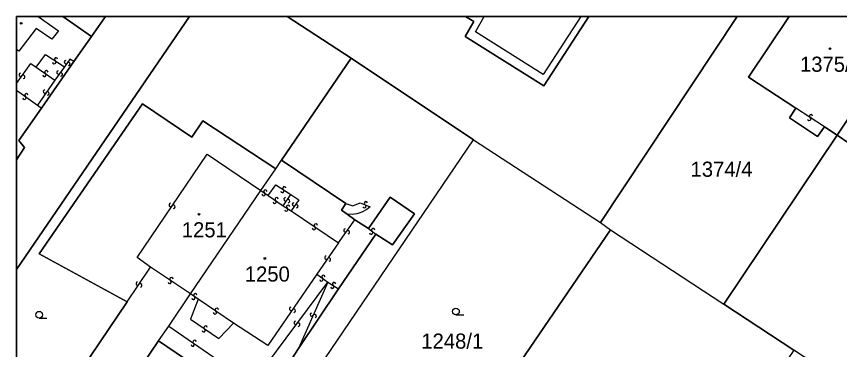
# Model space of a CAD drawing. Extents: x -600309 to -598967, y -1161267 to -1160292.
# Drawn here: x -600308.5 to -600216.2, y -1160329.8 to -1160292.3 of the extents above; entities that cross this region are included whole.
import ezdxf

# ---------------------------------------------------------------- set-up
doc = ezdxf.new("R2010")
doc.units = 0
for name, color, linetype in [('Level 1', 7, 'Continuous'), ('Level 13', 7, 'Continuous'), ('Level 3', 7, 'Continuous'), ('Level 4', 7, 'Continuous'), ('Level 5', 7, 'Continuous'), ('Level 60', 7, 'Continuous'), ('Vrstva 60', 7, 'Continuous'), ('Vrstva 63', 7, 'Continuous')]:
    doc.layers.add(name, color=color, linetype=linetype)

msp = doc.modelspace()

# ---------------------------------------------------------------- linework, layer by layer
at = {"layer": 'Level 1'}
for p, q in [((-600308.541, -1160320.794), (-600289.118, -1160292.347)), ((-600300.1, -1160294.6), (-600303.32, -1160292.347)), ((-600300.1, -1160294.6), (-600298.537, -1160292.347)), ((-600278.146, -1160292.347), (-600270.99, -1160297.05)), ((-600227.64, -1160292.347), (-600242.97, -1160315.51)), ((-600308.541, -1160342.846), (-600296.1, -1160324.42))]:
    msp.add_line(p, q, dxfattribs=at)
for points in [[(-600258.153, -1160292.347), (-600257.22, -1160292.93), (-600258.19, -1160294.6), (-600249.34, -1160300.14), (-600244.296, -1160292.347)], [(-600221.08, -1160302.65), (-600226.37, -1160299.17), (-600221.804, -1160292.347)], [(-600302.09, -1160297.42), (-600300.1, -1160294.6)], [(-600208.74, -1160294.23), (-600216.43, -1160305.71)], [(-600305.73, -1160302.65), (-600302.09, -1160297.42)], [(-600278.78, -1160308.52), (-600270.99, -1160297.05)], [(-600270.99, -1160297.05), (-600257.23, -1160306.23)], [(-600308.541, -1160308.453), (-600307.62, -1160307.07), (-600308.28, -1160306.3), (-600305.73, -1160302.65)], [(-600296.1, -1160324.42), (-600306, -1160319.03), (-600294.41, -1160302.17), (-600288.87, -1160305.93), (-600287.64, -1160304.09), (-600279.44, -1160309.47)], [(-600221.08, -1160302.65), (-600221.79, -1160303.73), (-600218.63, -1160305.86), (-600217.85, -1160304.77)], [(-600217.85, -1160304.77), (-600216.43, -1160305.71)], [(-600216.43, -1160305.71), (-600229.14, -1160324.7)], [(-600216.43, -1160305.71), (-600215.1, -1160306.58)], [(-600293.32, -1160359.44), (-600257.23, -1160306.23)], [(-600257.23, -1160306.23), (-600242.97, -1160315.51)], [(-600279.44, -1160309.47), (-600278.78, -1160308.52)], [(-600271.58, -1160313.38), (-600278.78, -1160308.52)], [(-600281.11, -1160311.9), (-600279.44, -1160309.47)], [(-600289, -1160323.54), (-600281.11, -1160311.9)], [(-600268.21, -1160316.83), (-600266.32, -1160318.03), (-600263.88, -1160314.52), (-600266.59, -1160312.66), (-600269.04, -1160316.19)], [(-600271.42, -1160314.57), (-600272.07, -1160314.13), (-600271.58, -1160313.38)], [(-600270.55, -1160315.2), (-600271.42, -1160314.57)], [(-600269.04, -1160316.19), (-600270.55, -1160315.2)], [(-600242.97, -1160315.51), (-600241.86, -1160316.33)], [(-600282.85, -1160376.42), (-600241.86, -1160316.33)], [(-600272.38, -1160322.95), (-600268.21, -1160316.83)], [(-600241.86, -1160316.33), (-600229.14, -1160324.7)], [(-600276.88, -1160329.68), (-600272.38, -1160322.95)], [(-600291.44, -1160327.18), (-600289, -1160323.54)], [(-600229.14, -1160324.7), (-600221.27, -1160329.87)], [(-600292.59, -1160328.82), (-600291.44, -1160327.18)], [(-600307.43, -1160350.76), (-600292.59, -1160328.82)], [(-600292.59, -1160328.82), (-600286.75, -1160332.8), (-600281.32, -1160334.59)], [(-600279.81, -1160334.2), (-600276.88, -1160329.68)]]:
    msp.add_lwpolyline(points, dxfattribs=at)
at = {"layer": 'Level 13'}
for centre, start, end in [((-600304.312, -1160297.483), 183.90701, 56.49701), ((-600304.107, -1160297.177), 4.12147, 236.21946), ((-600303, -1160297.484), 92.25578, 324.84578), ((-600302.7, -1160297.697), 272.47024, 144.56824), ((-600308.068, -1160298.91), 91.28301, 323.38101), ((-600307.772, -1160299.129), 271.06856, 143.65856), ((-600305.396, -1160298.921), 182.40614, 54.99614), ((-600305.183, -1160298.619), 2.6206, 234.71859), ((-600303.847, -1160298.65), 90.53695, 323.12695), ((-600303.553, -1160298.871), 270.75141, 142.8494), ((-600307.432, -1160301.2), 2.21265, 234.31065), ((-600305.362, -1160300.795), 92.8145, 325.4045), ((-600305.059, -1160301.005), 273.02895, 145.12695), ((-600307.647, -1160301.5), 181.99819, 54.58819), ((-600219.563, -1160303.863), 184.09397, 56.19197), ((-600219.358, -1160303.557), 3.87951, 236.46951), ((-600280.804, -1160312.332), 183.15079, 55.74079), ((-600280.595, -1160312.028), 3.36524, 235.46324), ((-600278.692, -1160311.973), 183.62781, 56.21781), ((-600278.487, -1160311.667), 3.84226, 235.94026), ((-600279.556, -1160313.191), 182.37402, 54.96402), ((-600279.343, -1160312.889), 2.58847, 234.68647), ((-600278.342, -1160312.895), 93.15703, 325.25503), ((-600278.038, -1160313.104), 272.94258, 145.53258), ((-600291.222, -1160313.535), 93.31946, 325.41746), ((-600290.918, -1160313.744), 273.10501, 145.69501), ((-600278.248, -1160314.056), 185.37736, 57.96736), ((-600278.051, -1160313.744), 5.59182, 237.68982), ((-600277.41, -1160313.474), 92.19753, 324.78753), ((-600277.11, -1160313.687), 272.41199, 144.50999), ((-600269.469, -1160313.691), 195.53508, 68.12508), ((-600269.33, -1160313.349), 15.74954, 247.84753), ((-600274.944, -1160315.849), 2.93796, 235.03596), ((-600275.155, -1160316.151), 182.72351, 55.31351), ((-600271.629, -1160316.392), 91.8974, 323.9954), ((-600271.331, -1160316.607), 271.68295, 144.27295), ((-600268.733, -1160316.655), 179.52303, 52.11303), ((-600268.506, -1160316.365), 359.73748, 231.83548), ((-600273.761, -1160319.455), 92.79549, 325.38549), ((-600273.459, -1160319.666), 273.00995, 145.10794), ((-600274.091, -1160321.622), 1.48409, 233.58209), ((-600294.942, -1160322.376), 93.41161, 325.5096), ((-600294.638, -1160322.583), 273.19715, 145.78715), ((-600291.344, -1160322.192), 183.47657, 55.57456), ((-600291.137, -1160321.888), 3.26211, 235.85211), ((-600274.309, -1160321.919), 181.26963, 53.85963), ((-600272.882, -1160322.424), 5.71198, 237.80998), ((-600273.077, -1160322.736), 185.49753, 58.08753), ((-600288.676, -1160323.991), 182.9208, 55.0188), ((-600288.465, -1160323.689), 2.70634, 235.29634), ((-600286.056, -1160325.328), 2.93863, 235.52863), ((-600277.721, -1160325.215), 92.50411, 325.09411), ((-600286.265, -1160325.632), 183.15308, 55.25108), ((-600277.419, -1160325.426), 272.71857, 144.81656), ((-600275.398, -1160325.865), 103.32401, 335.91401), ((-600275.062, -1160326.016), 283.53847, 155.63647), ((-600277.207, -1160326.778), 90.69922, 322.79722), ((-600276.913, -1160327.001), 270.48477, 143.07477), ((-600287.524, -1160327.622), 182.97676, 55.56676), ((-600287.315, -1160327.318), 3.19122, 235.28922), ((-600288.554, -1160328.929), 2.97389, 235.07189), ((-600288.765, -1160329.231), 182.75943, 55.34943)]:
    msp.add_arc(centre, 0.184, start, end, dxfattribs=at)
at = {"layer": 'Level 3'}
msp.add_line((-600308.541, -1160300.64), (-600306.17, -1160302.31), dxfattribs=at)
for points in [[(-600306.088, -1160292.347), (-600306.09, -1160292.35), (-600303.84, -1160293.95), (-600304.57, -1160294.9), (-600306.32, -1160293.71), (-600308.27, -1160296.25), (-600308.541, -1160296.057)], [(-600245.181, -1160292.347), (-600249.42, -1160298.88), (-600257.02, -1160294.06), (-600256.028, -1160292.347)], [(-600306.34, -1160298.05), (-600305.27, -1160296.63), (-600303.15, -1160298.02)], [(-600302.09, -1160297.42), (-600302.55, -1160297.16), (-600303.15, -1160298.02)], [(-600308.541, -1160299.874), (-600306.92, -1160297.65), (-600306.34, -1160298.05)], [(-600306.34, -1160298.05), (-600304.25, -1160299.5)], [(-600303.15, -1160298.02), (-600304.25, -1160299.5)], [(-600304.25, -1160299.5), (-600306.17, -1160302.31)], [(-600306.17, -1160302.31), (-600305.73, -1160302.65)], [(-600217.85, -1160304.77), (-600221.08, -1160302.65)], [(-600293.48, -1160320.53), (-600294.99, -1160319.44), (-600287.15, -1160307.84), (-600281.11, -1160311.9)], [(-600280.28, -1160312.46), (-600279.42, -1160311.27), (-600277.76, -1160312.37)], [(-600281.11, -1160311.9), (-600280.28, -1160312.46)], [(-600280.28, -1160312.46), (-600278.61, -1160313.62)], [(-600278.61, -1160313.62), (-600277.76, -1160312.37)], [(-600277.76, -1160312.37), (-600276.83, -1160312.96), (-600277.69, -1160314.19)], [(-600278.61, -1160313.62), (-600277.69, -1160314.19)], [(-600271.58, -1160313.38), (-600270.77, -1160313.64), (-600269.96, -1160313.3), (-600268.85, -1160313.74), (-600269.22, -1160314.04), (-600269.76, -1160314.33), (-600270.33, -1160314.52), (-600270.86, -1160314.6), (-600271.42, -1160314.57)], [(-600277.69, -1160314.19), (-600272.41, -1160317.81)], [(-600272.41, -1160317.81), (-600270.55, -1160315.2)], [(-600269.04, -1160316.19), (-600268.21, -1160316.83)], [(-600272.41, -1160317.81), (-600274.81, -1160321.32)], [(-600296.1, -1160324.42), (-600293.48, -1160320.53)], [(-600289, -1160323.54), (-600293.48, -1160320.53)], [(-600274.81, -1160321.32), (-600280.34, -1160329.32), (-600284.17, -1160326.83)], [(-600274.81, -1160321.32), (-600273.58, -1160322.21)], [(-600280.55, -1160331.57), (-600273.58, -1160322.21)], [(-600273.58, -1160322.21), (-600276.88, -1160329.68)], [(-600273.58, -1160322.21), (-600272.38, -1160322.95)], [(-600288.14, -1160324.13), (-600289.02, -1160326.38), (-600285.81, -1160328.56), (-600284.17, -1160326.83)], [(-600288.14, -1160324.13), (-600289, -1160323.54)], [(-600284.17, -1160326.83), (-600288.14, -1160324.13)], [(-600291.44, -1160327.18), (-600285.89, -1160330.98), (-600282.03, -1160331.97)]]:
    msp.add_lwpolyline(points, dxfattribs=at)
at = {"layer": 'Level 5'}
for p, q in [((-600259.21, -1160325.89), (-600258.335, -1160325.89)), ((-600306, -1160326.25), (-600305.125, -1160326.25))]:
    msp.add_line(p, q, dxfattribs=at)
for centre, radius in [((-600308.01, -1160293.12), 0.09), ((-600308.01, -1160293.12), 0.0521), ((-600217.23, -1160295.96), 0.09), ((-600217.23, -1160295.96), 0.0521), ((-600288.06, -1160314.58), 0.09), ((-600288.06, -1160314.58), 0.0521), ((-600280.66, -1160319.55), 0.09), ((-600280.66, -1160319.55), 0.0521), ((-600259.21, -1160325.515), 0.375), ((-600306, -1160325.875), 0.375)]:
    msp.add_circle(centre, radius, dxfattribs=at)
at = {"layer": 'Level 60'}
for points in [[(-600215.1, -1160306.58), (-600216.43, -1160305.71), (-600208.74, -1160294.23), (-600207.56, -1160292.47), (-600206.49, -1160293.18), (-600207.6, -1160294.96)], [(-600241.86, -1160316.33), (-600282.85, -1160376.42), (-600288.31, -1160372.2), (-600284.15, -1160366.82), (-600286.84, -1160364.74), (-600289.61, -1160362.6), (-600289.47, -1160362.42), (-600293.32, -1160359.44), (-600257.23, -1160306.23), (-600242.97, -1160315.51)], [(-600286.75, -1160332.8), (-600292.59, -1160328.82), (-600291.44, -1160327.18), (-600289, -1160323.54), (-600281.11, -1160311.9), (-600279.44, -1160309.47), (-600278.78, -1160308.52), (-600271.58, -1160313.38), (-600272.07, -1160314.13), (-600271.42, -1160314.57), (-600270.55, -1160315.2), (-600269.04, -1160316.19), (-600266.59, -1160312.66), (-600263.88, -1160314.52), (-600266.32, -1160318.03), (-600268.21, -1160316.83), (-600272.38, -1160322.95), (-600276.88, -1160329.68), (-600279.81, -1160334.2), (-600281.32, -1160334.59)], [(-600262.97, -1160391.13), (-600263.15, -1160391.32), (-600264.98, -1160389.81), (-600274.67, -1160382.53), (-600274.96, -1160382.3), (-600282.85, -1160376.42), (-600241.86, -1160316.33), (-600229.14, -1160324.7), (-600221.27, -1160329.87)]]:
    msp.add_lwpolyline(points, close=True, dxfattribs=at)
msp.add_lwpolyline([(-600199.77, -1160343.98), (-600221.27, -1160329.87), (-600229.14, -1160324.7), (-600216.43, -1160305.71), (-600215.1, -1160306.58)], dxfattribs=at)
at = {"layer": 'Vrstva 60'}
for points in [[(-600303.32, -1160292.347), (-600308.541, -1160292.347), (-600308.541, -1160308.453), (-600307.62, -1160307.07), (-600308.28, -1160306.3), (-600305.73, -1160302.65), (-600302.09, -1160297.42), (-600300.1, -1160294.6)], [(-600308.541, -1160320.794), (-600308.541, -1160342.846), (-600296.1, -1160324.42), (-600306, -1160319.03), (-600294.41, -1160302.17), (-600288.87, -1160305.93), (-600287.64, -1160304.09), (-600279.44, -1160309.47), (-600278.78, -1160308.52), (-600270.99, -1160297.05), (-600278.146, -1160292.347), (-600289.118, -1160292.347)], [(-600308.541, -1160308.453), (-600308.541, -1160320.794), (-600289.118, -1160292.347), (-600298.537, -1160292.347), (-600300.1, -1160294.6), (-600302.09, -1160297.42), (-600305.73, -1160302.65), (-600308.28, -1160306.3), (-600307.62, -1160307.07)], [(-600298.537, -1160292.347), (-600303.32, -1160292.347), (-600300.1, -1160294.6)], [(-600227.64, -1160292.347), (-600244.296, -1160292.347), (-600249.34, -1160300.14), (-600258.19, -1160294.6), (-600257.22, -1160292.93), (-600258.153, -1160292.347), (-600278.146, -1160292.347), (-600270.99, -1160297.05), (-600257.23, -1160306.23), (-600242.97, -1160315.51)], [(-600244.296, -1160292.347), (-600258.153, -1160292.347), (-600257.22, -1160292.93), (-600258.19, -1160294.6), (-600249.34, -1160300.14)], [(-600221.804, -1160292.347), (-600227.64, -1160292.347), (-600242.97, -1160315.51), (-600241.86, -1160316.33), (-600229.14, -1160324.7), (-600216.43, -1160305.71), (-600217.85, -1160304.77), (-600218.63, -1160305.86), (-600221.79, -1160303.73), (-600221.08, -1160302.65), (-600226.37, -1160299.17)], [(-600207.745, -1160292.347), (-600221.804, -1160292.347), (-600226.37, -1160299.17), (-600221.08, -1160302.65), (-600221.79, -1160303.73), (-600218.63, -1160305.86), (-600217.85, -1160304.77), (-600216.43, -1160305.71), (-600208.74, -1160294.23), (-600207.56, -1160292.47)], [(-600308.541, -1160342.846), (-600308.541, -1160352.373), (-600307.43, -1160350.76), (-600292.59, -1160328.82), (-600291.44, -1160327.18), (-600289, -1160323.54), (-600281.11, -1160311.9), (-600279.44, -1160309.47), (-600287.64, -1160304.09), (-600288.87, -1160305.93), (-600294.41, -1160302.17), (-600306, -1160319.03), (-600296.1, -1160324.42)]]:
    msp.add_lwpolyline(points, close=True, dxfattribs=at)
for points in [[(-600293.32, -1160359.44), (-600257.23, -1160306.23), (-600270.99, -1160297.05), (-600278.78, -1160308.52), (-600271.58, -1160313.38), (-600272.07, -1160314.13), (-600271.42, -1160314.57), (-600270.55, -1160315.2), (-600269.04, -1160316.19), (-600266.59, -1160312.66), (-600263.88, -1160314.52), (-600266.32, -1160318.03), (-600268.21, -1160316.83), (-600272.38, -1160322.95), (-600276.88, -1160329.68), (-600279.81, -1160334.2)], [(-600286.75, -1160332.8), (-600292.59, -1160328.82), (-600307.43, -1160350.76)]]:
    msp.add_lwpolyline(points, dxfattribs=at)
at = {"layer": 'Vrstva 63'}
msp.add_lwpolyline([(-600308.541, -1160292.347), (-598967.108, -1160292.347), (-598967.108, -1161267.031), (-600308.541, -1161267.031)], close=True, dxfattribs=at)

# ---------------------------------------------------------------- texts
at = {"layer": 'Level 4'}
for s, p in [('1375/2', (-600220.598, -1160298.57)), ('1374/4', (-600232.882, -1160310.37)), ('1251', (-600289.985, -1160317.18)), ('1250', (-600282.915, -1160322.15)), ('1248/1', (-600263.102, -1160329.69))]:
    msp.add_text(s, height=1.7, dxfattribs=at).set_placement(p)

doc.saveas('drawing.dxf')
